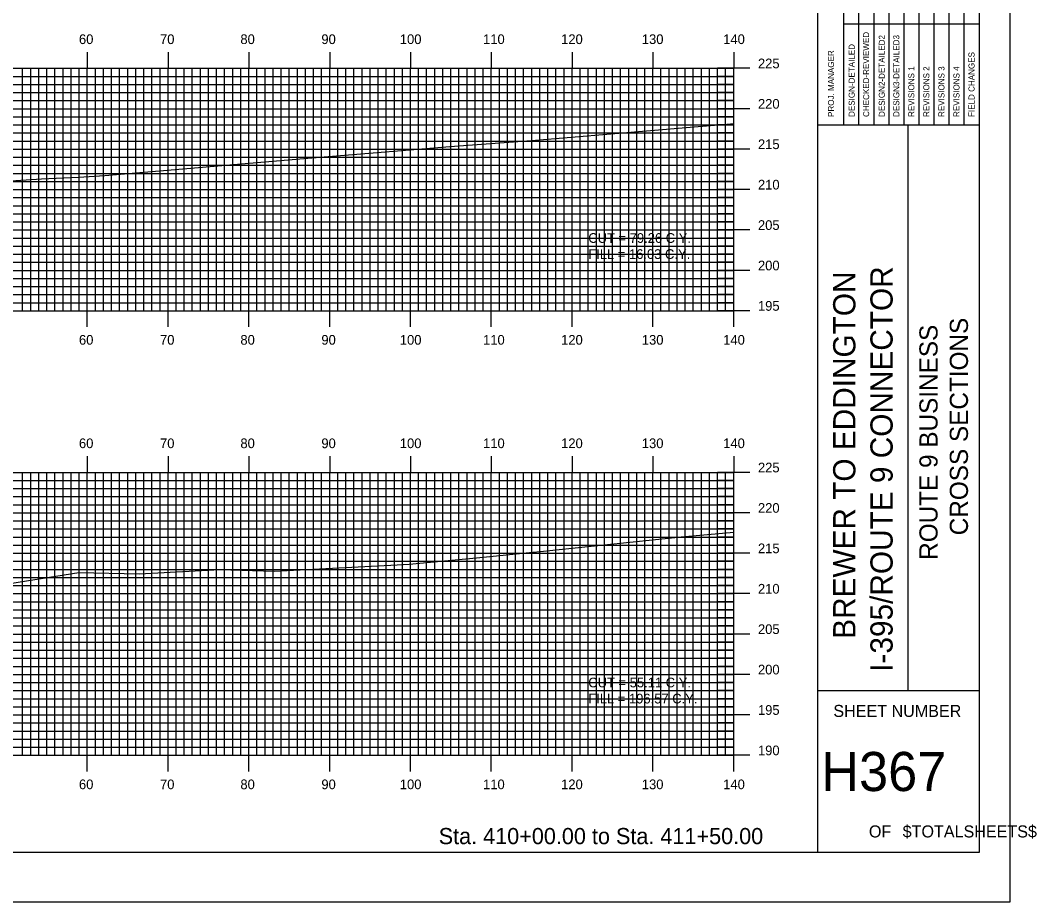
# Model space of a CAD drawing. Extents: x 853316 to 853659, y 364785 to 365005.
# Drawn here: x 853533.5 to 853659.3, y 364785.1 to 364894.2 of the extents above; entities that cross this region are included whole.
import ezdxf

# ---------------------------------------------------------------- set-up
doc = ezdxf.new("R2010")
doc.units = 0
for name, color, linetype in [('BORDER', 7, 'Continuous'), ('D_Text_Standard', 7, 'Continuous'), ('H_V ANNOTATION', 7, 'Continuous'), ('MAJOR', 7, 'Continuous'), ('MINOR', 7, 'Continuous'), ('PLOT BOUNDARY', 7, 'Continuous'), ('S_Roadway_Centerline', 7, 'Continuous')]:
    doc.layers.add(name, color=color, linetype=linetype)

msp = doc.modelspace()

# ---------------------------------------------------------------- linework, layer by layer
at = {"layer": 'BORDER'}
for p, q in [((853632.16, 364791.23), (853632.16, 365001.23)), ((853632.16, 364881.24), (853652.16, 364881.24)), ((853643.34, 364811.24), (853643.34, 364881.24)), ((853632.16, 364811.24), (853652.16, 364811.24))]:
    msp.add_line(p, q, dxfattribs=at)
msp.add_lwpolyline([(853332.16, 364791.23), (853652.16, 364791.23), (853652.16, 365001.23), (853332.16, 365001.23)], close=True, dxfattribs=at)
for points in [[(853637.25, 364881.24), (853637.25, 364916.24)], [(853639.12, 364916.24), (853639.12, 364881.24)], [(853640.98, 364881.24), (853640.98, 364916.24)], [(853642.84, 364881.24), (853642.84, 364916.24)], [(853644.71, 364881.24), (853644.71, 364916.24)], [(853646.57, 364881.24), (853646.57, 364916.24)], [(853648.43, 364881.24), (853648.43, 364916.24)], [(853650.3, 364881.24), (853650.3, 364916.24)], [(853635.39, 364881.24), (853635.39, 364914.83)], [(853635.39, 364893.74), (853652.16, 364893.74)]]:
    msp.add_lwpolyline(points, dxfattribs=at)
at = {"layer": 'MAJOR'}
for p, q in [((853541.76, 364890.24), (853541.76, 364888.23)), ((853551.76, 364890.24), (853551.76, 364888.23)), ((853561.76, 364890.24), (853561.76, 364888.23)), ((853571.76, 364890.24), (853571.76, 364888.23)), ((853581.76, 364890.24), (853581.76, 364888.23)), ((853591.76, 364890.24), (853591.76, 364888.23)), ((853601.76, 364890.24), (853601.76, 364888.23)), ((853611.76, 364890.24), (853611.76, 364888.23)), ((853621.76, 364890.24), (853621.76, 364888.23)), ((853341.76, 364888.23), (853621.76, 364888.23)), ((853341.76, 364888.23), (853621.76, 364888.23)), ((853541.76, 364858.23), (853541.76, 364888.23)), ((853551.76, 364858.23), (853551.76, 364888.23)), ((853561.76, 364858.23), (853561.76, 364888.23)), ((853571.76, 364858.23), (853571.76, 364888.23)), ((853581.76, 364858.23), (853581.76, 364888.23)), ((853591.76, 364858.23), (853591.76, 364888.23)), ((853601.76, 364858.23), (853601.76, 364888.23)), ((853611.76, 364858.23), (853611.76, 364888.23)), ((853623.76, 364888.23), (853619.75, 364888.23)), ((853621.76, 364858.23), (853621.76, 364888.23)), ((853621.76, 364858.23), (853621.76, 364888.23)), ((853341.76, 364883.23), (853621.76, 364883.23)), ((853623.76, 364883.23), (853619.75, 364883.23)), ((853341.76, 364878.23), (853621.76, 364878.23)), ((853623.76, 364878.23), (853619.75, 364878.23)), ((853341.76, 364873.23), (853621.76, 364873.23)), ((853623.76, 364873.23), (853619.75, 364873.23)), ((853341.76, 364868.23), (853621.76, 364868.23)), ((853623.76, 364868.23), (853619.75, 364868.23)), ((853341.76, 364863.23), (853621.76, 364863.23)), ((853623.76, 364863.23), (853619.75, 364863.23)), ((853341.76, 364858.23), (853621.76, 364858.23)), ((853341.76, 364858.23), (853621.76, 364858.23)), ((853541.76, 364856.23), (853541.76, 364858.23)), ((853551.76, 364856.23), (853551.76, 364858.23)), ((853561.76, 364856.23), (853561.76, 364858.23)), ((853571.76, 364856.23), (853571.76, 364858.23)), ((853581.76, 364856.23), (853581.76, 364858.23)), ((853591.76, 364856.23), (853591.76, 364858.23)), ((853601.76, 364856.23), (853601.76, 364858.23)), ((853611.76, 364856.23), (853611.76, 364858.23)), ((853623.76, 364858.23), (853619.75, 364858.23)), ((853621.76, 364856.23), (853621.76, 364858.23)), ((853541.76, 364840.24), (853541.76, 364838.23)), ((853551.76, 364840.24), (853551.76, 364838.23)), ((853561.76, 364840.24), (853561.76, 364838.23)), ((853571.76, 364840.24), (853571.76, 364838.23)), ((853581.76, 364840.24), (853581.76, 364838.23)), ((853591.76, 364840.24), (853591.76, 364838.23)), ((853601.76, 364840.24), (853601.76, 364838.23)), ((853611.76, 364840.24), (853611.76, 364838.23)), ((853621.76, 364840.24), (853621.76, 364838.23)), ((853341.76, 364838.23), (853621.76, 364838.23)), ((853341.76, 364838.23), (853621.76, 364838.23)), ((853541.76, 364803.23), (853541.76, 364838.23)), ((853551.76, 364803.23), (853551.76, 364838.23)), ((853561.76, 364803.23), (853561.76, 364838.23)), ((853571.76, 364803.23), (853571.76, 364838.23)), ((853581.76, 364803.23), (853581.76, 364838.23)), ((853591.76, 364803.23), (853591.76, 364838.23)), ((853601.76, 364803.23), (853601.76, 364838.23)), ((853611.76, 364803.23), (853611.76, 364838.23)), ((853623.76, 364838.23), (853619.75, 364838.23)), ((853621.76, 364803.23), (853621.76, 364838.23)), ((853621.76, 364803.23), (853621.76, 364838.23)), ((853341.76, 364833.23), (853621.76, 364833.23)), ((853623.76, 364833.23), (853619.75, 364833.23)), ((853341.76, 364828.23), (853621.76, 364828.23)), ((853623.76, 364828.23), (853619.75, 364828.23)), ((853341.76, 364823.23), (853621.76, 364823.23)), ((853623.76, 364823.23), (853619.75, 364823.23)), ((853341.76, 364818.23), (853621.76, 364818.23)), ((853623.76, 364818.23), (853619.75, 364818.23)), ((853341.76, 364813.23), (853621.76, 364813.23)), ((853623.76, 364813.23), (853619.75, 364813.23)), ((853341.76, 364808.23), (853621.76, 364808.23)), ((853623.76, 364808.23), (853619.75, 364808.23)), ((853341.76, 364803.23), (853621.76, 364803.23)), ((853341.76, 364803.23), (853621.76, 364803.23)), ((853541.76, 364801.23), (853541.76, 364803.23)), ((853551.76, 364801.23), (853551.76, 364803.23)), ((853561.76, 364801.23), (853561.76, 364803.23)), ((853571.76, 364801.23), (853571.76, 364803.23)), ((853581.76, 364801.23), (853581.76, 364803.23)), ((853591.76, 364801.23), (853591.76, 364803.23)), ((853601.76, 364801.23), (853601.76, 364803.23)), ((853611.76, 364801.23), (853611.76, 364803.23)), ((853623.76, 364803.23), (853619.75, 364803.23)), ((853621.76, 364801.23), (853621.76, 364803.23))]:
    msp.add_line(p, q, dxfattribs=at)
at = {"layer": 'MINOR'}
for p, q in [((853533.76, 364858.23), (853533.76, 364888.23)), ((853534.76, 364858.23), (853534.76, 364888.23)), ((853535.76, 364858.23), (853535.76, 364888.23)), ((853536.76, 364858.23), (853536.76, 364888.23)), ((853537.76, 364858.23), (853537.76, 364888.23)), ((853538.76, 364858.23), (853538.76, 364888.23)), ((853539.76, 364858.23), (853539.76, 364888.23)), ((853540.76, 364858.23), (853540.76, 364888.23)), ((853542.76, 364858.23), (853542.76, 364888.23)), ((853543.76, 364858.23), (853543.76, 364888.23)), ((853544.76, 364858.23), (853544.76, 364888.23)), ((853545.76, 364858.23), (853545.76, 364888.23)), ((853546.76, 364858.23), (853546.76, 364888.23)), ((853547.76, 364858.23), (853547.76, 364888.23)), ((853548.76, 364858.23), (853548.76, 364888.23)), ((853549.76, 364858.23), (853549.76, 364888.23)), ((853550.76, 364858.23), (853550.76, 364888.23)), ((853552.76, 364858.23), (853552.76, 364888.23)), ((853553.76, 364858.23), (853553.76, 364888.23)), ((853554.76, 364858.23), (853554.76, 364888.23)), ((853555.76, 364858.23), (853555.76, 364888.23)), ((853556.76, 364858.23), (853556.76, 364888.23)), ((853557.76, 364858.23), (853557.76, 364888.23)), ((853558.76, 364858.23), (853558.76, 364888.23)), ((853559.76, 364858.23), (853559.76, 364888.23)), ((853560.76, 364858.23), (853560.76, 364888.23)), ((853562.76, 364858.23), (853562.76, 364888.23)), ((853563.76, 364858.23), (853563.76, 364888.23)), ((853564.76, 364858.23), (853564.76, 364888.23)), ((853565.76, 364858.23), (853565.76, 364888.23)), ((853566.76, 364858.23), (853566.76, 364888.23)), ((853567.76, 364858.23), (853567.76, 364888.23)), ((853568.76, 364858.23), (853568.76, 364888.23)), ((853569.76, 364858.23), (853569.76, 364888.23)), ((853570.76, 364858.23), (853570.76, 364888.23)), ((853572.76, 364858.23), (853572.76, 364888.23)), ((853573.76, 364858.23), (853573.76, 364888.23)), ((853574.76, 364858.23), (853574.76, 364888.23)), ((853575.76, 364858.23), (853575.76, 364888.23)), ((853576.76, 364858.23), (853576.76, 364888.23)), ((853577.76, 364858.23), (853577.76, 364888.23)), ((853578.76, 364858.23), (853578.76, 364888.23)), ((853579.76, 364858.23), (853579.76, 364888.23)), ((853580.76, 364858.23), (853580.76, 364888.23)), ((853582.76, 364858.23), (853582.76, 364888.23)), ((853583.76, 364858.23), (853583.76, 364888.23)), ((853584.76, 364858.23), (853584.76, 364888.23)), ((853585.76, 364858.23), (853585.76, 364888.23)), ((853586.76, 364858.23), (853586.76, 364888.23)), ((853587.76, 364858.23), (853587.76, 364888.23)), ((853588.76, 364858.23), (853588.76, 364888.23)), ((853589.76, 364858.23), (853589.76, 364888.23)), ((853590.76, 364858.23), (853590.76, 364888.23)), ((853592.76, 364858.23), (853592.76, 364888.23)), ((853593.76, 364858.23), (853593.76, 364888.23)), ((853594.76, 364858.23), (853594.76, 364888.23)), ((853595.76, 364858.23), (853595.76, 364888.23)), ((853596.76, 364858.23), (853596.76, 364888.23)), ((853597.76, 364858.23), (853597.76, 364888.23)), ((853598.76, 364858.23), (853598.76, 364888.23)), ((853599.76, 364858.23), (853599.76, 364888.23)), ((853600.76, 364858.23), (853600.76, 364888.23)), ((853602.76, 364858.23), (853602.76, 364888.23)), ((853603.76, 364858.23), (853603.76, 364888.23)), ((853604.76, 364858.23), (853604.76, 364888.23)), ((853605.76, 364858.23), (853605.76, 364888.23)), ((853606.76, 364858.23), (853606.76, 364888.23)), ((853607.76, 364858.23), (853607.76, 364888.23)), ((853608.76, 364858.23), (853608.76, 364888.23)), ((853609.76, 364858.23), (853609.76, 364888.23)), ((853610.76, 364858.23), (853610.76, 364888.23)), ((853612.76, 364858.23), (853612.76, 364888.23)), ((853613.76, 364858.23), (853613.76, 364888.23)), ((853614.76, 364858.23), (853614.76, 364888.23)), ((853615.76, 364858.23), (853615.76, 364888.23)), ((853616.76, 364858.23), (853616.76, 364888.23)), ((853617.76, 364858.23), (853617.76, 364888.23)), ((853618.76, 364858.23), (853618.76, 364888.23)), ((853619.76, 364858.23), (853619.76, 364888.23)), ((853620.76, 364858.23), (853620.76, 364888.23)), ((853341.76, 364887.23), (853621.76, 364887.23)), ((853621.76, 364887.23), (853619.75, 364887.23)), ((853341.76, 364886.23), (853621.76, 364886.23)), ((853621.76, 364886.23), (853619.75, 364886.23)), ((853341.76, 364885.23), (853621.76, 364885.23)), ((853341.76, 364884.23), (853621.76, 364884.23)), ((853621.76, 364885.23), (853619.75, 364885.23)), ((853621.76, 364884.23), (853619.75, 364884.23)), ((853341.76, 364882.23), (853621.76, 364882.23)), ((853621.76, 364882.23), (853619.75, 364882.23)), ((853341.76, 364881.23), (853621.76, 364881.23)), ((853621.76, 364881.23), (853619.75, 364881.23)), ((853341.76, 364880.23), (853621.76, 364880.23)), ((853341.76, 364879.23), (853621.76, 364879.23)), ((853621.76, 364880.23), (853619.75, 364880.23)), ((853621.76, 364879.23), (853619.75, 364879.23)), ((853341.76, 364877.23), (853621.76, 364877.23)), ((853621.76, 364877.23), (853619.75, 364877.23)), ((853341.76, 364876.23), (853621.76, 364876.23)), ((853621.76, 364876.23), (853619.75, 364876.23)), ((853341.76, 364875.23), (853621.76, 364875.23)), ((853341.76, 364874.23), (853621.76, 364874.23)), ((853621.76, 364875.23), (853619.75, 364875.23)), ((853621.76, 364874.23), (853619.75, 364874.23)), ((853341.76, 364872.23), (853621.76, 364872.23)), ((853621.76, 364872.23), (853619.75, 364872.23)), ((853341.76, 364871.23), (853621.76, 364871.23)), ((853621.76, 364871.23), (853619.75, 364871.23)), ((853341.76, 364870.23), (853621.76, 364870.23)), ((853341.76, 364869.23), (853621.76, 364869.23)), ((853621.76, 364870.23), (853619.75, 364870.23)), ((853621.76, 364869.23), (853619.75, 364869.23)), ((853341.76, 364867.23), (853621.76, 364867.23)), ((853621.76, 364867.23), (853619.75, 364867.23)), ((853341.76, 364866.23), (853621.76, 364866.23)), ((853621.76, 364866.23), (853619.75, 364866.23)), ((853341.76, 364865.23), (853621.76, 364865.23)), ((853341.76, 364864.23), (853621.76, 364864.23)), ((853621.76, 364865.23), (853619.75, 364865.23)), ((853621.76, 364864.23), (853619.75, 364864.23)), ((853341.76, 364862.23), (853621.76, 364862.23)), ((853621.76, 364862.23), (853619.75, 364862.23)), ((853341.76, 364861.23), (853621.76, 364861.23)), ((853621.76, 364861.23), (853619.75, 364861.23)), ((853341.76, 364860.23), (853621.76, 364860.23)), ((853341.76, 364859.23), (853621.76, 364859.23)), ((853621.76, 364860.23), (853619.75, 364860.23)), ((853621.76, 364859.23), (853619.75, 364859.23)), ((853533.76, 364803.23), (853533.76, 364838.23)), ((853534.76, 364803.23), (853534.76, 364838.23)), ((853535.76, 364803.23), (853535.76, 364838.23)), ((853536.76, 364803.23), (853536.76, 364838.23)), ((853537.76, 364803.23), (853537.76, 364838.23)), ((853538.76, 364803.23), (853538.76, 364838.23)), ((853539.76, 364803.23), (853539.76, 364838.23)), ((853540.76, 364803.23), (853540.76, 364838.23)), ((853542.76, 364803.23), (853542.76, 364838.23)), ((853543.76, 364803.23), (853543.76, 364838.23)), ((853544.76, 364803.23), (853544.76, 364838.23)), ((853545.76, 364803.23), (853545.76, 364838.23)), ((853546.76, 364803.23), (853546.76, 364838.23)), ((853547.76, 364803.23), (853547.76, 364838.23)), ((853548.76, 364803.23), (853548.76, 364838.23)), ((853549.76, 364803.23), (853549.76, 364838.23)), ((853550.76, 364803.23), (853550.76, 364838.23)), ((853552.76, 364803.23), (853552.76, 364838.23)), ((853553.76, 364803.23), (853553.76, 364838.23)), ((853554.76, 364803.23), (853554.76, 364838.23)), ((853555.76, 364803.23), (853555.76, 364838.23)), ((853556.76, 364803.23), (853556.76, 364838.23)), ((853557.76, 364803.23), (853557.76, 364838.23)), ((853558.76, 364803.23), (853558.76, 364838.23)), ((853559.76, 364803.23), (853559.76, 364838.23)), ((853560.76, 364803.23), (853560.76, 364838.23)), ((853562.76, 364803.23), (853562.76, 364838.23)), ((853563.76, 364803.23), (853563.76, 364838.23)), ((853564.76, 364803.23), (853564.76, 364838.23)), ((853565.76, 364803.23), (853565.76, 364838.23)), ((853566.76, 364803.23), (853566.76, 364838.23)), ((853567.76, 364803.23), (853567.76, 364838.23)), ((853568.76, 364803.23), (853568.76, 364838.23)), ((853569.76, 364803.23), (853569.76, 364838.23)), ((853570.76, 364803.23), (853570.76, 364838.23)), ((853572.76, 364803.23), (853572.76, 364838.23)), ((853573.76, 364803.23), (853573.76, 364838.23)), ((853574.76, 364803.23), (853574.76, 364838.23)), ((853575.76, 364803.23), (853575.76, 364838.23)), ((853576.76, 364803.23), (853576.76, 364838.23)), ((853577.76, 364803.23), (853577.76, 364838.23)), ((853578.76, 364803.23), (853578.76, 364838.23)), ((853579.76, 364803.23), (853579.76, 364838.23)), ((853580.76, 364803.23), (853580.76, 364838.23)), ((853582.76, 364803.23), (853582.76, 364838.23)), ((853583.76, 364803.23), (853583.76, 364838.23)), ((853584.76, 364803.23), (853584.76, 364838.23)), ((853585.76, 364803.23), (853585.76, 364838.23)), ((853586.76, 364803.23), (853586.76, 364838.23)), ((853587.76, 364803.23), (853587.76, 364838.23)), ((853588.76, 364803.23), (853588.76, 364838.23)), ((853589.76, 364803.23), (853589.76, 364838.23)), ((853590.76, 364803.23), (853590.76, 364838.23)), ((853592.76, 364803.23), (853592.76, 364838.23)), ((853593.76, 364803.23), (853593.76, 364838.23)), ((853594.76, 364803.23), (853594.76, 364838.23)), ((853595.76, 364803.23), (853595.76, 364838.23)), ((853596.76, 364803.23), (853596.76, 364838.23)), ((853597.76, 364803.23), (853597.76, 364838.23)), ((853598.76, 364803.23), (853598.76, 364838.23)), ((853599.76, 364803.23), (853599.76, 364838.23)), ((853600.76, 364803.23), (853600.76, 364838.23)), ((853602.76, 364803.23), (853602.76, 364838.23)), ((853603.76, 364803.23), (853603.76, 364838.23)), ((853604.76, 364803.23), (853604.76, 364838.23)), ((853605.76, 364803.23), (853605.76, 364838.23)), ((853606.76, 364803.23), (853606.76, 364838.23)), ((853607.76, 364803.23), (853607.76, 364838.23)), ((853608.76, 364803.23), (853608.76, 364838.23)), ((853609.76, 364803.23), (853609.76, 364838.23)), ((853610.76, 364803.23), (853610.76, 364838.23)), ((853612.76, 364803.23), (853612.76, 364838.23)), ((853613.76, 364803.23), (853613.76, 364838.23)), ((853614.76, 364803.23), (853614.76, 364838.23)), ((853615.76, 364803.23), (853615.76, 364838.23)), ((853616.76, 364803.23), (853616.76, 364838.23)), ((853617.76, 364803.23), (853617.76, 364838.23)), ((853618.76, 364803.23), (853618.76, 364838.23)), ((853619.76, 364803.23), (853619.76, 364838.23)), ((853620.76, 364803.23), (853620.76, 364838.23)), ((853341.76, 364837.23), (853621.76, 364837.23)), ((853621.76, 364837.23), (853619.75, 364837.23)), ((853341.76, 364836.23), (853621.76, 364836.23)), ((853341.76, 364835.23), (853621.76, 364835.23)), ((853621.76, 364836.23), (853619.75, 364836.23)), ((853621.76, 364835.23), (853619.75, 364835.23)), ((853341.76, 364834.23), (853621.76, 364834.23)), ((853621.76, 364834.23), (853619.75, 364834.23)), ((853341.76, 364832.23), (853621.76, 364832.23)), ((853621.76, 364832.23), (853619.75, 364832.23)), ((853341.76, 364831.23), (853621.76, 364831.23)), ((853341.76, 364830.23), (853621.76, 364830.23)), ((853621.76, 364831.23), (853619.75, 364831.23)), ((853621.76, 364830.23), (853619.75, 364830.23)), ((853341.76, 364829.23), (853621.76, 364829.23)), ((853621.76, 364829.23), (853619.75, 364829.23)), ((853341.76, 364827.23), (853621.76, 364827.23)), ((853621.76, 364827.23), (853619.75, 364827.23)), ((853341.76, 364826.23), (853621.76, 364826.23)), ((853341.76, 364825.23), (853621.76, 364825.23)), ((853621.76, 364826.23), (853619.75, 364826.23)), ((853621.76, 364825.23), (853619.75, 364825.23)), ((853341.76, 364824.23), (853621.76, 364824.23)), ((853621.76, 364824.23), (853619.75, 364824.23)), ((853341.76, 364822.23), (853621.76, 364822.23)), ((853621.76, 364822.23), (853619.75, 364822.23)), ((853341.76, 364821.23), (853621.76, 364821.23)), ((853341.76, 364820.23), (853621.76, 364820.23)), ((853621.76, 364821.23), (853619.75, 364821.23)), ((853621.76, 364820.23), (853619.75, 364820.23)), ((853341.76, 364819.23), (853621.76, 364819.23)), ((853621.76, 364819.23), (853619.75, 364819.23)), ((853341.76, 364817.23), (853621.76, 364817.23)), ((853621.76, 364817.23), (853619.75, 364817.23)), ((853341.76, 364816.23), (853621.76, 364816.23)), ((853341.76, 364815.23), (853621.76, 364815.23)), ((853621.76, 364816.23), (853619.75, 364816.23)), ((853621.76, 364815.23), (853619.75, 364815.23)), ((853341.76, 364814.23), (853621.76, 364814.23)), ((853621.76, 364814.23), (853619.75, 364814.23)), ((853341.76, 364812.23), (853621.76, 364812.23)), ((853341.76, 364811.23), (853621.76, 364811.23)), ((853621.76, 364812.23), (853619.75, 364812.23)), ((853621.76, 364811.23), (853619.75, 364811.23)), ((853341.76, 364810.23), (853621.76, 364810.23)), ((853621.76, 364810.23), (853619.75, 364810.23)), ((853341.76, 364809.23), (853621.76, 364809.23)), ((853621.76, 364809.23), (853619.75, 364809.23)), ((853341.76, 364807.23), (853621.76, 364807.23)), ((853341.76, 364806.23), (853621.76, 364806.23)), ((853621.76, 364807.23), (853619.75, 364807.23)), ((853621.76, 364806.23), (853619.75, 364806.23)), ((853341.76, 364805.23), (853621.76, 364805.23)), ((853621.76, 364805.23), (853619.75, 364805.23)), ((853341.76, 364804.23), (853621.76, 364804.23)), ((853621.76, 364804.23), (853619.75, 364804.23))]:
    msp.add_line(p, q, dxfattribs=at)
at = {"layer": 'PLOT BOUNDARY'}
msp.add_lwpolyline([(853315.97, 364785.11), (853655.97, 364785.11), (853655.97, 365005.11), (853315.97, 365005.11)], close=True, dxfattribs=at)
at = {"layer": 'S_Roadway_Centerline'}
for points in [[(853529.02, 364874.09), (853536.1, 364874.57), (853540.67, 364874.76), (853543.92, 364874.97), (853568.55, 364877.07), (853582.66, 364878.24), (853586.63, 364878.57), (853596.72, 364879.29), (853616.39, 364880.96), (853620.89, 364881.3), (853621.76, 364881.39)], [(853516.88, 364822.05), (853540.71, 364825.86), (853548.2, 364825.68), (853558.22, 364826.21), (853564.87, 364826.02), (853580.13, 364826.78), (853581.59, 364826.86), (853589.92, 364827.66), (853596.89, 364828.35), (853597.85, 364828.45), (853599.37, 364828.62), (853615.26, 364830.27), (853621.76, 364830.85)]]:
    msp.add_lwpolyline(points, dxfattribs=at)

# ---------------------------------------------------------------- texts
at = {"layer": 'BORDER'}
for s, height, p in [('CHECKED-REVIEWED', 0.7455, (853638.52, 364882.21)), ('DESIGN2-DETAILED2', 0.7455, (853640.46, 364882.21)), ('DESIGN3-DETAILED3', 0.7455, (853642.25, 364882.21)), ('DESIGN-DETAILED', 0.7455, (853636.73, 364882.21)), ('PROJ. MANAGER', 0.7455, (853634.17, 364882.21)), ('FIELD CHANGES', 0.7455, (853651.56, 364882.21)), ('REVISIONS 1', 0.7455, (853644.11, 364882.21)), ('REVISIONS 2', 0.7455, (853645.97, 364882.21)), ('REVISIONS 3', 0.7455, (853647.84, 364882.21)), ('REVISIONS 4', 0.7455, (853649.7, 364882.21)), ('I-395/ROUTE 9 CONNECTOR', 2.7557, (853641.43, 364813.56)), ('BREWER TO EDDINGTON', 2.7557, (853636.82, 364817.64)), ('CROSS SECTIONS', 2.25, (853650.75, 364830.45)), ('ROUTE 9 BUSINESS', 2.25, (853646.99, 364827.41))]:
    msp.add_text(s, height=height, rotation=90, dxfattribs=at).set_placement(p)
for s, height, p in [('SHEET NUMBER', 1.4905, (853634.09, 364807.97)), ('H367', 4.839, (853632.6, 364798.8)), ('OF', 1.491, (853638.49, 364793.06)), ('$TOTALSHEETS$', 1.4905, (853642.67, 364793.06))]:
    msp.add_text(s, height=height, dxfattribs=at).set_placement(p)
at = {"layer": 'D_Text_Standard'}
for s, p in [('CUT = 79.26 C.Y.', (853603.76, 364866.63)), ('FILL = 16.03 C.Y.', (853603.76, 364864.64)), ('CUT = 55.11 C.Y.', (853603.76, 364811.63)), ('FILL = 196.57 C.Y.', (853603.76, 364809.64))]:
    msp.add_text(s, height=1.2, dxfattribs=at).set_placement(p)
at = {"layer": 'H_V ANNOTATION'}
for s, height, p in [('60', 1.2, (853540.73, 364891.23)), ('70', 1.2, (853550.76, 364891.23)), ('80', 1.2, (853560.71, 364891.23)), ('90', 1.2, (853570.73, 364891.23)), ('100', 1.2, (853580.44, 364891.23)), ('110', 1.2, (853590.74, 364891.23)), ('120', 1.2, (853600.4, 364891.23)), ('130', 1.2, (853610.39, 364891.23)), ('140', 1.2, (853620.46, 364891.23)), ('225', 1.2, (853624.76, 364888.23)), ('220', 1.2, (853624.76, 364883.23)), ('215', 1.2, (853624.76, 364878.23)), ('210', 1.2, (853624.76, 364873.23)), ('205', 1.2, (853624.76, 364868.23)), ('200', 1.2, (853624.76, 364863.23)), ('195', 1.2, (853624.76, 364858.23)), ('60', 1.2, (853540.73, 364854.03)), ('70', 1.2, (853550.76, 364854.03)), ('80', 1.2, (853560.71, 364854.03)), ('90', 1.2, (853570.73, 364854.03)), ('100', 1.2, (853580.44, 364854.03)), ('110', 1.2, (853590.74, 364854.03)), ('120', 1.2, (853600.4, 364854.03)), ('130', 1.2, (853610.39, 364854.03)), ('140', 1.2, (853620.46, 364854.03)), ('60', 1.2, (853540.73, 364841.23)), ('70', 1.2, (853550.76, 364841.23)), ('80', 1.2, (853560.71, 364841.23)), ('90', 1.2, (853570.73, 364841.23)), ('100', 1.2, (853580.44, 364841.23)), ('110', 1.2, (853590.74, 364841.23)), ('120', 1.2, (853600.4, 364841.23)), ('130', 1.2, (853610.39, 364841.23)), ('140', 1.2, (853620.46, 364841.23)), ('225', 1.2, (853624.76, 364838.23)), ('220', 1.2, (853624.76, 364833.23)), ('215', 1.2, (853624.76, 364828.23)), ('210', 1.2, (853624.76, 364823.23)), ('205', 1.2, (853624.76, 364818.23)), ('200', 1.2, (853624.76, 364813.23)), ('195', 1.2, (853624.76, 364808.23)), ('190', 1.2, (853624.76, 364803.23)), ('60', 1.2, (853540.73, 364799.03)), ('70', 1.2, (853550.76, 364799.03)), ('80', 1.2, (853560.71, 364799.03)), ('90', 1.2, (853570.73, 364799.03)), ('100', 1.2, (853580.44, 364799.03)), ('110', 1.2, (853590.74, 364799.03)), ('120', 1.2, (853600.4, 364799.03)), ('130', 1.2, (853610.39, 364799.03)), ('140', 1.2, (853620.46, 364799.03)), ('Sta. 410+00.00 to Sta. 411+50.00', 2.0004, (853585.25, 364792.23))]:
    msp.add_text(s, height=height, dxfattribs=at).set_placement(p)

doc.saveas('drawing.dxf')
